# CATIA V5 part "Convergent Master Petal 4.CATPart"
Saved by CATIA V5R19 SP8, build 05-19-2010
Part number: Convergent Master Petal 4
Bounding box of the stored display mesh (mm): x -20 to 20, y 521.635 to 738.365, z 391.635 to 608.365
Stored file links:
  G:\EU_thinkMotion\CFAO_2010\MMS_groupe3\MMS_groupe3\A reprendre\fovide\fovide\Convergent Master Petal 4.CATPart
  G:\EU_thinkMotion\CFAO_2010\MMS_groupe3\MMS_groupe3\A reprendre\fovide\fovide\fovide.CATProduct
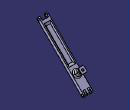
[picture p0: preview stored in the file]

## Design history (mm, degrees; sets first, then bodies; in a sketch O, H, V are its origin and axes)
Set1
  Plane1: linked copy from another document
  Line1 to Line3: linked copy from another document
  Plane2: linked copy from another document
  Plane3: linked copy from another document
  Point1 "Point.J": linked copy from another document
  Line4: linked copy from another document
Body1 (main body)
  Sketch1 on Plane1, origin (0, 565, 565), H (1, 0, 0), V (0, -0.7071, 0.7071)
    line L1 (20, 57.4975) -> (20, -241.3452)
    line L2 (-20, -241.3452) -> (-20, 57.4975)
    line L3 (-20, -241.3452) -> (-14, -241.3452)
    line L4 (-14, -241.3452) -> (-14, -221.3452)
    line L5 (-14, -221.3452) -> (-5, -221.3452)
    line L6 (-5, -221.3452) -> (-5, -241.3452)
    point P8 (-5, -241.3452)
    line L7 (-5, -241.3452) -> (5, -241.3452)
    line L8 (5, -241.3452) -> (5, -221.3452)
    point P10 (5, -221.3452)
    line L9 (5, -221.3452) -> (14, -221.3452)
    line L10 (14, -221.3452) -> (14, -241.3452)
    point P12 (14, -241.3452)
    line L11 (14, -241.3452) -> (20, -241.3452)
    reference projected line E1 (-150, -233.3452) -> (150, -233.3452) from Line1
    reference projected line E2 (0, -233.3452) -> (0, 49.4975) from Line2
    line L12 (-20, 57.4975) -> (-14, 57.4975)
    line L13 (-14, 57.4975) -> (-14, 41.4975)
    line L14 (-14, 41.4975) -> (14, 41.4975)
    line L15 (14, 41.4975) -> (14, 57.4975)
    point P16 (14, 57.4975)
    line L16 (14, 57.4975) -> (20, 57.4975)
    reference projected line E3 (-150, 49.4975) -> (150, 49.4975) from Line3
    length L10 = 20
    distance L11 E1 = 8
    length L9 = 9
    length L5 = 9
    length L7 = 10
    distance L8 E2 = 5
    length L11 = 6
    length L3 = 6
    length L16 = 6
    length L12 = 6
    length L15 = 16
    distance L16 E3 = 8
    vertical: L1 V, L2 V, L4 V, L6 V, L8 V, L10 V, L13 V, L15 V
    horizontal: L3 H, L5 H, L7 H, L9 H, L11 H, L12 H, L14 H, L16 H
    coincidence: P8 L3, P10 L5, P12 L3, L9 L5, L3 L7, L7 L11, P16 L12, L16 L12
  Pad1: profile Sketch1, direction (0, -0.7071, -0.7071), length 7, mirrored extent
  Fillet1: radius 5, on edge [start face of Pad1 | face of Pad1 from Sketch1.L11]; edge [start face of Pad1 | face of Pad1 from Sketch1.L7]; edge [start face of Pad1 | face of Pad1 from Sketch1.L3]; edge [face of Pad1 from Sketch1.L3 | end face of Pad1]; edge [face of Pad1 from Sketch1.L7 | end face of Pad1]; edge [face of Pad1 from Sketch1.L11 | end face of Pad1]; edge [start face of Pad1 | face of Pad1 from Sketch1.L12]; edge [start face of Pad1 | face of Pad1 from Sketch1.L16]; edge [face of Pad1 from Sketch1.L16 | end face of Pad1]; edge [face of Pad1 from Sketch1.L12 | end face of Pad1]
  Sketch2 on start face of Pad1, origin (0, 569.9497, 569.9497), H (-1, 0, 0), V (0, -0.7071, 0.7071)
    line L1 (-15, 29.4975) -> (15, 29.4975)
    line L2 (15, 29.4975) -> (15, -133.3452)
    line L3 (15, -133.3452) -> (-15, -133.3452)
    line L4 (-15, -133.3452) -> (-15, 29.4975)
    reference projected line E1 (0, -233.3452) -> (0, 49.4975) from Line2
    reference projected line E2 (150, 49.4975) -> (-150, 49.4975) from Line3
    reference projected line E3 (150, -233.3452) -> (-150, -233.3452) from Line1
    distance L2 E1 = 15
    length L1 = 30
    distance E2 L1 = 20
    distance E3 L3 = 100
    horizontal: L1 H, L3 H
    vertical: L2 V, L4 V
  Sketch3 on Plane2, origin (0, 567.1213, 567.1213), H (1, 0, 0), V (0, -0.7071, 0.7071)
    line L1 (-10, 19.4975) -> (10, 19.4975)
    line L2 (10, 19.4975) -> (10, -123.3452)
    line L3 (10, -123.3452) -> (-10, -123.3452)
    line L4 (-10, -123.3452) -> (-10, 19.4975)
    reference projected line E1 (0, -233.3452) -> (0, 49.4975) from Line2
    reference projected line E2 (-150, 49.4975) -> (150, 49.4975) from Line3
    reference projected line E3 (-150, -233.3452) -> (150, -233.3452) from Line1
    distance L2 E1 = 10
    length L1 = 20
    distance L1 E2 = 30
    distance E3 L3 = 110
    horizontal: L1 H, L3 H
    vertical: L2 V, L4 V
  Loft1: solid, Sections (Sketch2; Sketch3)
  Sketch4 on end face of Pad1, origin (0, 560.0503, 560.0503), H (1, 0, 0), V (0, -0.7071, 0.7071)
    line L1 (-15, 29.4975) -> (15, 29.4975)
    line L2 (15, 29.4975) -> (15, -213.3452)
    line L3 (15, -213.3452) -> (-15, -213.3452)
    line L4 (-15, -213.3452) -> (-15, 29.4975)
    reference projected line E1 (0, -233.3452) -> (0, 49.4975) from Line2
    reference projected line E2 (-150, 49.4975) -> (150, 49.4975) from Line3
    reference projected line E3 (-150, -233.3452) -> (150, -233.3452) from Line1
    distance E1 L2 = 15
    length L1 = 30
    distance E2 L1 = 20
    distance E3 L3 = 20
    horizontal: L1 H, L3 H
    vertical: L2 V, L4 V
  Sketch5 on Plane3, origin (0, 562.8787, 562.8787), H (1, 0, 0), V (0, -0.7071, 0.7071)
    line L1 (-10, 19.4975) -> (10, 19.4975)
    line L2 (10, 19.4975) -> (10, -203.3452)
    line L3 (10, -203.3452) -> (-10, -203.3452)
    line L4 (-10, -203.3452) -> (-10, 19.4975)
    reference projected line E1 (-150, 49.4975) -> (150, 49.4975) from Line3
    reference projected line E2 (-150, -233.3452) -> (150, -233.3452) from Line1
    reference projected line E3 (0, -233.3452) -> (0, 49.4975) from Line2
    distance L1 E1 = 30
    distance E2 L3 = 30
    distance L2 E3 = 10
    length L1 = 20
    horizontal: L1 H, L3 H
    vertical: L2 V, L4 V
  Loft2: solid, Sections (Sketch4; Sketch5)
  Sketch6 on face of Pad1 from Sketch1.L1, origin (20, 730, 400), H (0, 1, 0), V (0, 0, 1)
    point P1 (0, 0)
    intersected point E1 (0, 0) from Line1
    coincidence: E1 P1
  Hole1: placed by Sketch6, at (20, 730, 400) direction (-1, 0, 0), diameter 10, through (limit type 3)
  Sketch7 on face of Pad1 from Sketch1.L1, origin (20, 530, 600), H (0, 1, 0), V (0, 0, 1)
    point P1 (0, 0)
    intersected point E1 (0, 0) from Line3
    coincidence: E1 P1
  Hole2: placed by Sketch7, at (20, 530, 600) direction (-1, 0, 0), diameter 10, through (limit type 3)
  Sketch8 on start face of Pad1, origin (0, 569.9497, 569.9497), H (-1, 0, 0), V (0, -0.7071, 0.7071)
    circle A1 centre (0, -162.6346) radius 12.5
    point P1 (0, -162.6346)
    reference projected point E1 (0, -162.6346) from Point1
    radius A1 = 12.5
    coincidence: P1 E1
  Pad2: profile Sketch8, direction (0, 0.7071, 0.7071), length 20
  Sketch9 on end face of Pad2, origin (0, 584.0919, 584.0919), H (-1, 0, 0), V (0, -0.7071, 0.7071)
    circle A1 centre (0, -162.6346) radius 7.5
    point P1 (0, -162.6346)
    reference projected point E1 (0, -162.6346) from Point1
    radius A1 = 7.5
    coincidence: P1 E1
  Pad3: profile Sketch9, direction (0, 0.7071, 0.7071), length 15
  Fillet2: radius 5, on edge [start face of Pad1 | face of Pad2 from Sketch8.A1]
  Sketch10 on end face of Pad3, origin (0, 594.6985, 594.6985), H (-1, 0, 0), V (0, -0.7071, 0.7071)
    line L1 (-12.5, -150.1346) -> (12.5, -150.1346)
    line L2 (12.5, -150.1346) -> (12.5, -175.1346)
    line L3 (12.5, -175.1346) -> (-12.5, -175.1346)
    line L4 (-12.5, -175.1346) -> (-12.5, -150.1346)
    reference projected point E1 (0, -162.6346) from Point1
    reference projected point E2 (0, -162.6346) from Point1
    length L2 = 25
    length L3 = 25
    distance L1 E1 = 12.5
    distance L2 E2 = 12.5
    horizontal: L1 H, L3 H
    vertical: L2 V, L4 V
  Pad4: profile Sketch10, direction (0, 0.7071, 0.7071), length 3
  Fillet3: radius 5, on edge [face of Pad4 from Sketch10.L4 | face of Pad4 from Sketch10.L1]; edge [face of Pad4 from Sketch10.L3 | face of Pad4 from Sketch10.L4]; edge [face of Pad4 from Sketch10.L2 | face of Pad4 from Sketch10.L3]; edge [face of Pad4 from Sketch10.L1 | face of Pad4 from Sketch10.L2]
  Sketch11 on end face of Pad4, origin (0, 711.8198, 481.8198), H (1, 0, 0), V (0, 0.7071, -0.7071)
    point P1 (0, 0)
    intersected point E1 (0, 0) from Line4
    coincidence: E1 P1
  Hole3: placed by Sketch11, at (0, 711.8198, 481.8198) direction (0, -0.7071, -0.7071), diameter 10, depth 3
  Sketch12 on face of Hole3, origin (0, 594.6985, 594.6985), H (-1, 0, 0), V (0, -0.7071, 0.7071)
    point P1 (0, -162.6346)
    point P2 (-0.0046, -166.6346)
    point P3 (3.4618, -164.6385)
    point P4 (3.4664, -160.6385)
    point P5 (0.0046, -158.6346)
    point P6 (-3.4618, -160.6306)
    point P7 (-3.4664, -164.6306)
    point P8 (1.7286, -165.6365)
    line L1 (-0.0046, -166.6346) -> (3.4618, -164.6385)
    line L2 (3.4618, -164.6385) -> (3.4664, -160.6385)
    line L3 (3.4664, -160.6385) -> (0.0046, -158.6346)
    line L4 (0.0046, -158.6346) -> (-3.4618, -160.6306)
    line L5 (-3.4618, -160.6306) -> (-3.4664, -164.6306)
    line L6 (-3.4664, -164.6306) -> (-0.0046, -166.6346)
    construction line L7 (0, -162.6346) -> (1.7286, -165.6365)
    construction circle A1 centre (0, -162.6346) radius 4
    construction arc A2 centre (-3.4618, -160.6306) radius 4 from (0.0046, -158.6346) to (-3.4664, -164.6306) cw
    construction arc A3 centre (3.4618, -164.6385) radius 4 from (3.4664, -160.6385) to (-0.0046, -166.6346) ccw
    reference projected point E1 (0, -162.6346) from Point1
    radius A1 = 4
    coincidence: A1 P2, A1 P3, A1 P4, A1 P5, A1 P6, A1 P7, A2 P1, A3 P1, P1 E1
    midpoint: P8 L1
    parallelism: L1 L4
  Pad5: profile Sketch12, direction (0, 0.7071, 0.7071), length 3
